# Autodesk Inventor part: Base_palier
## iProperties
Shininess: 64.0
Length Units: 11269
Angle Units: 11279
Time Units: 11290
Mass Units: 11283
Length Display Precision: 3
Angle Display Precision: 2
Compacted: True
Part Number: Base_palier
Document SubType Name: Modeling
Created: 2008-02
Material: Acier inoxydable - 440C
Designer: Pascal
Density: 0.0
Volumn: 0.0
Area: 0.0
PropertySet Name: Model Information
Control State: 0
Master: False
Checked Out: False
DESIGNATION: pièce
Author: Pascal
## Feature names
1. Révolution1 [Revolution]
